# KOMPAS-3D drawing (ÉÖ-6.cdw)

Referenced files in F:\1я детская\: РЩ-6.cdw
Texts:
  Реконструкция элеткроснабжения помещений 2 го этажа  первой детской городской больницы
  Microsoft
  Текст на чертеже
  Размерные надписи
  Шероховатость
  Линия-выноска #1
  Линия-выноска #2
  Линия-выноска #3
  Отклонения формы и база
  Заголовок таблицы
  Ячейка таблицы
  Стрелка вида
  Обозначение изменения
  Фигурная скобка
  Номер узла
  Марка координационной оси
  VRCB
  Выносная надпись
  Обозначение узла
  Марка/позиционное обозначение с линией-выноской
  Марка/позиционное обозначение на линии
  Марка/позиционное обозначение без линии-выноски
  ВА 47-29 (1)
  ВА 47-29 (3)
  Номер группы
  Р кВт
  Ток, А
  Гр42
  Гр43
  Гр44
  Гр45
  Освещение
  ВВГнгLS 5х10 мм 2  скрыто в ст.
  гофр. трубе от ВРУ
  РЩ-6 (ЩРВ-24)
  Гр46
  Гр47
  Бактарецидные
  лампы
  Гр56
  Розетки
  Гр57
  АД12М
  ВВГнгLS 3х1,5 cкрыто
  ВВГнгLS 3х2,5 cкрыто
  CONTINUOUS0
  Реконструкция элеткроснабжения помещений 2 го этажа
  первой детской городской больницы
  ГИП
  Разработ
  Однолинейная схема щита РЩ6
Dimensions and other numbers on the sheet: 7; 10А; 16А; 0.5; 0.12; 0.24; 1.1; 1.0; 5.05; 16А Iсраб=30мА; 1:1; 5; 0; 1; 2; 3; 4; 6; 8; 9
